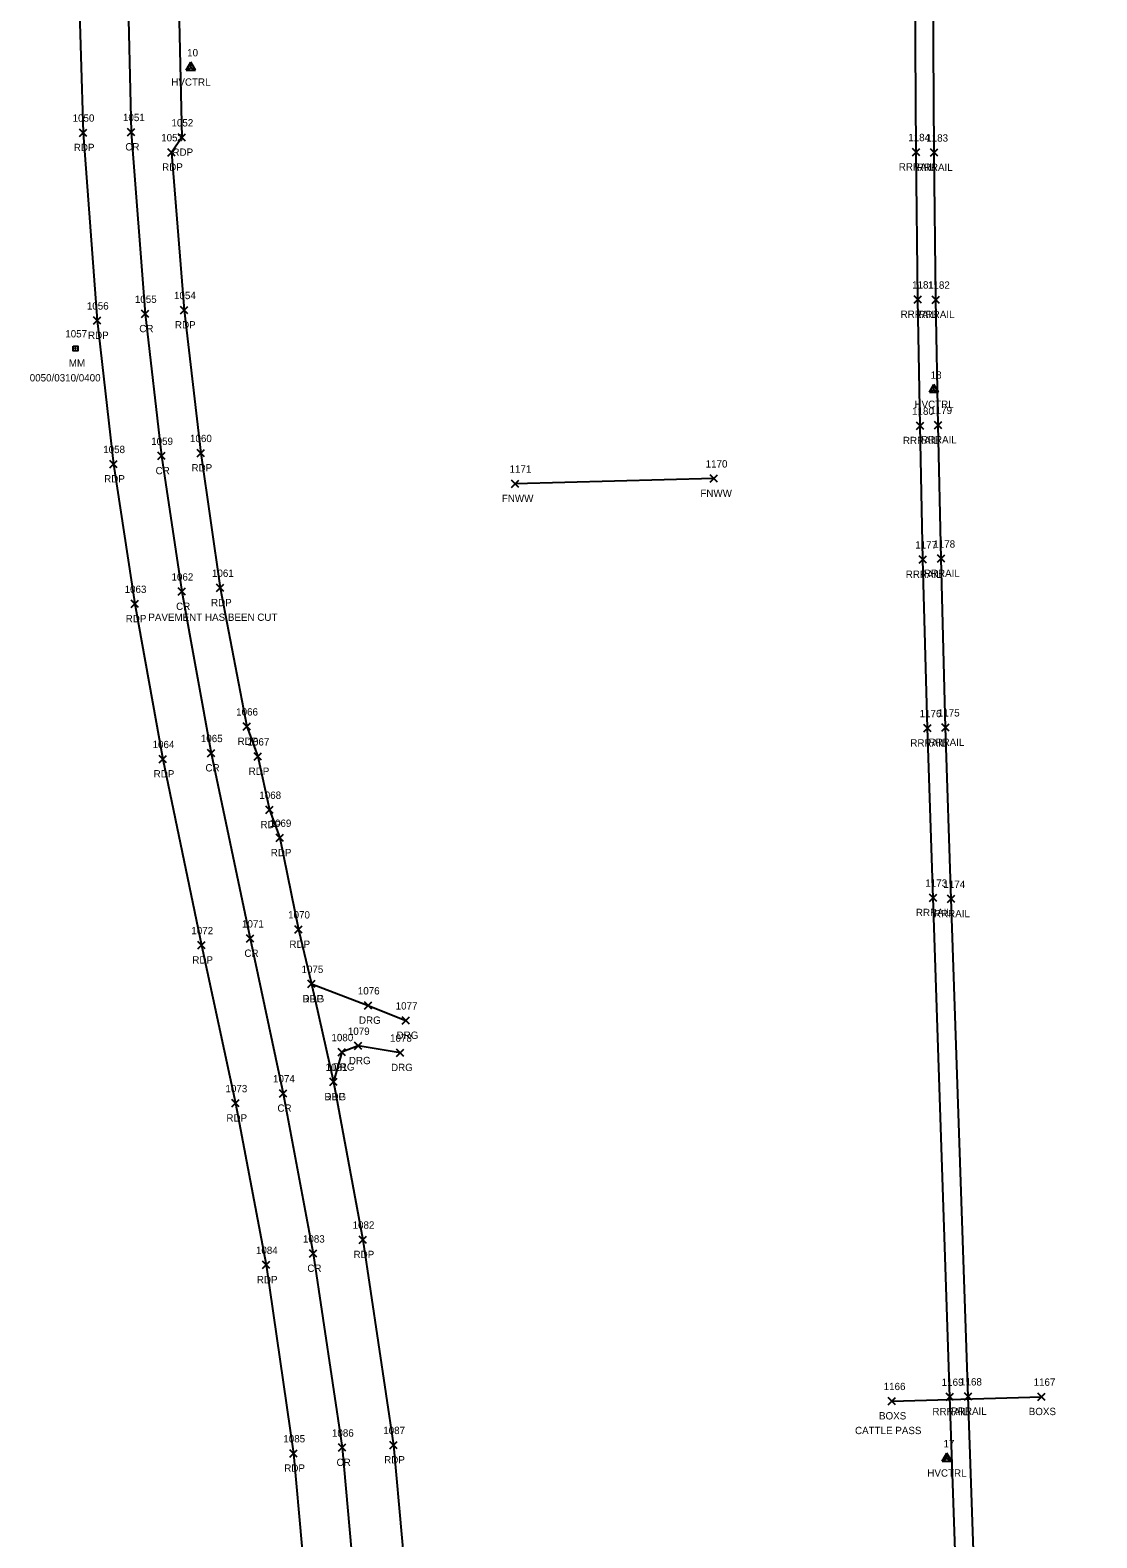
# Model space of a CAD drawing. Extents: x 1754529 to 1755810, y 621660 to 624656.
# Drawn here: x 1755362.7 to 1755653.8, y 622749.4 to 623160.6 of the extents above; entities that cross this region are included whole.
import ezdxf

# ---------------------------------------------------------------- set-up
doc = ezdxf.new("R2010")
doc.units = 0
for name, color, linetype in [('C_A', 7, 'Continuous'), ('C_I', 7, 'Continuous'), ('CPSM', 7, 'Continuous'), ('D_A', 7, 'Continuous'), ('D_C', 7, 'Continuous'), ('D_I', 7, 'Continuous'), ('D_TIC', 7, 'Continuous'), ('DDEFAULT', 7, 'Continuous'), ('L_A', 7, 'Continuous'), ('L_I', 7, 'Continuous'), ('L_TIC', 7, 'Continuous'), ('Level 14', 7, 'Continuous'), ('LFNC', 7, 'Continuous'), ('P_A', 7, 'Continuous'), ('P_C', 7, 'Continuous'), ('P_I', 7, 'Continuous'), ('PET', 7, 'Continuous'), ('PRC', 7, 'Continuous'), ('R_A', 7, 'Continuous'), ('R_I', 7, 'Continuous'), ('R_TIC', 7, 'Continuous'), ('RDG', 7, 'Continuous'), ('RR', 7, 'Continuous'), ('S_A', 7, 'Continuous'), ('S_C', 7, 'Continuous'), ('S_I', 7, 'Continuous'), ('SRM', 7, 'Continuous')]:
    doc.layers.add(name, color=color, linetype=linetype)

msp = doc.modelspace()

# ---------------------------------------------------------------- linework, layer by layer
at = {"layer": 'CPSM'}
for p, q in [((1755405.34, 623149.68), (1755406.59, 623151.85)), ((1755407.84, 623149.68), (1755406.59, 623151.85)), ((1755406.59, 623150.4), (1755406.59, 623151.85)), ((1755405.34, 623149.68), (1755406.59, 623150.4)), ((1755405.34, 623149.68), (1755407.84, 623149.68)), ((1755406.59, 623150.4), (1755406.59, 623150.4)), ((1755406.59, 623150.4), (1755407.84, 623149.68)), ((1755608.13, 623061.8), (1755609.38, 623063.97)), ((1755608.13, 623061.8), (1755609.38, 623062.52)), ((1755608.13, 623061.8), (1755610.63, 623061.8)), ((1755610.63, 623061.8), (1755609.38, 623063.97)), ((1755609.38, 623062.52), (1755609.38, 623063.97)), ((1755609.38, 623062.52), (1755609.38, 623062.52)), ((1755609.38, 623062.52), (1755610.63, 623061.8)), ((1755611.64, 622770.39), (1755612.89, 622772.56)), ((1755611.64, 622770.39), (1755612.89, 622771.12)), ((1755611.64, 622770.39), (1755614.14, 622770.39)), ((1755614.14, 622770.39), (1755612.89, 622772.56)), ((1755612.89, 622771.12), (1755612.89, 622772.56)), ((1755612.89, 622771.12), (1755612.89, 622771.12)), ((1755612.89, 622771.12), (1755614.14, 622770.39))]:
    msp.add_line(p, q, dxfattribs=at)
at = {"layer": 'D_TIC'}
for points in [[(1755596.89, 622785.72), (1755598.89, 622787.72)], [(1755598.89, 622785.72), (1755596.89, 622787.72)], [(1755637.74, 622786.9), (1755639.74, 622788.9)], [(1755639.74, 622786.9), (1755637.74, 622788.9)]]:
    msp.add_lwpolyline(points, dxfattribs=at)
at = {"layer": 'DDEFAULT'}
msp.add_lwpolyline([(1755597.89, 622786.72), (1755638.74, 622787.9)], dxfattribs=at)
at = {"layer": 'L_TIC'}
for points in [[(1755494.12, 623035.88), (1755496.12, 623037.88)], [(1755496.12, 623035.88), (1755494.12, 623037.88)], [(1755548.29, 623037.29), (1755550.29, 623039.29)], [(1755550.29, 623037.29), (1755548.29, 623039.29)]]:
    msp.add_lwpolyline(points, dxfattribs=at)
at = {"layer": 'Level 14'}
for points in [[(1755376.19, 623131.58), (1755378.19, 623133.58)], [(1755378.19, 623131.58), (1755376.19, 623133.58)], [(1755389.29, 623131.74), (1755391.29, 623133.74)], [(1755391.29, 623131.74), (1755389.29, 623133.74)], [(1755403.1, 623130.29), (1755405.1, 623132.29)], [(1755405.1, 623130.29), (1755403.1, 623132.29)], [(1755400.28, 623126.23), (1755402.28, 623128.23)], [(1755402.28, 623126.23), (1755400.28, 623128.23)], [(1755380.06, 623080.36), (1755382.06, 623082.36)], [(1755382.06, 623080.36), (1755380.06, 623082.36)], [(1755393.1, 623082.18), (1755395.1, 623084.18)], [(1755395.1, 623082.18), (1755393.1, 623084.18)], [(1755403.78, 623083.2), (1755405.78, 623085.2)], [(1755405.78, 623083.2), (1755403.78, 623085.2)], [(1755397.56, 623043.45), (1755399.56, 623045.45)], [(1755399.56, 623043.45), (1755397.56, 623045.45)], [(1755408.29, 623044.22), (1755410.29, 623046.22)], [(1755410.29, 623044.22), (1755408.29, 623046.22)], [(1755384.46, 623041.22), (1755386.46, 623043.22)], [(1755386.46, 623041.22), (1755384.46, 623043.22)], [(1755403.15, 623006.45), (1755405.15, 623008.45)], [(1755405.15, 623006.45), (1755403.15, 623008.45)], [(1755413.62, 623007.47), (1755415.62, 623009.47)], [(1755415.62, 623007.47), (1755413.62, 623009.47)], [(1755390.35, 623003.09), (1755392.35, 623005.09)], [(1755392.35, 623003.09), (1755390.35, 623005.09)], [(1755420.85, 622969.66), (1755422.85, 622971.66)], [(1755422.85, 622969.66), (1755420.85, 622971.66)], [(1755397.98, 622960.77), (1755399.98, 622962.77)], [(1755399.98, 622960.77), (1755397.98, 622962.77)], [(1755411.15, 622962.41), (1755413.15, 622964.41)], [(1755413.15, 622962.41), (1755411.15, 622964.41)], [(1755423.89, 622961.49), (1755425.89, 622963.49)], [(1755425.89, 622961.49), (1755423.89, 622963.49)], [(1755427.11, 622946.94), (1755429.11, 622948.94)], [(1755429.11, 622946.94), (1755427.11, 622948.94)], [(1755429.91, 622939.3), (1755431.91, 622941.3)], [(1755431.91, 622939.3), (1755429.91, 622941.3)], [(1755421.77, 622911.86), (1755423.77, 622913.86)], [(1755423.77, 622911.86), (1755421.77, 622913.86)], [(1755435.01, 622914.32), (1755437.01, 622916.32)], [(1755437.01, 622914.32), (1755435.01, 622916.32)], [(1755408.52, 622910.02), (1755410.52, 622912.02)], [(1755410.52, 622910.02), (1755408.52, 622912.02)], [(1755438.57, 622899.46), (1755440.57, 622901.46)], [(1755440.57, 622899.46), (1755438.57, 622901.46)], [(1755444.56, 622872.75), (1755446.56, 622874.75)], [(1755446.56, 622872.75), (1755444.56, 622874.75)], [(1755417.82, 622866.94), (1755419.82, 622868.94)], [(1755419.82, 622866.94), (1755417.82, 622868.94)], [(1755430.8, 622869.62), (1755432.8, 622871.62)], [(1755432.8, 622869.62), (1755430.8, 622871.62)], [(1755452.51, 622829.73), (1755454.51, 622831.73)], [(1755454.51, 622829.73), (1755452.51, 622831.73)], [(1755438.96, 622825.95), (1755440.96, 622827.95)], [(1755440.96, 622825.95), (1755438.96, 622827.95)], [(1755426.14, 622822.84), (1755428.14, 622824.84)], [(1755428.14, 622822.84), (1755426.14, 622824.84)], [(1755433.61, 622771.46), (1755435.61, 622773.46)], [(1755435.61, 622771.46), (1755433.61, 622773.46)], [(1755446.94, 622773.03), (1755448.94, 622775.03)], [(1755448.94, 622773.03), (1755446.94, 622775.03)], [(1755460.87, 622773.73), (1755462.87, 622775.73)], [(1755462.87, 622773.73), (1755460.87, 622775.73)]]:
    msp.add_lwpolyline(points, dxfattribs=at)
at = {"layer": 'LFNC'}
msp.add_lwpolyline([(1755549.29, 623038.29), (1755495.12, 623036.88)], dxfattribs=at)
at = {"layer": 'PET'}
for points in [[(1755375.95, 623174.43), (1755377.19, 623132.58), (1755381.06, 623081.36), (1755385.46, 623042.22), (1755391.35, 623004.09), (1755398.98, 622961.77), (1755409.52, 622911.02), (1755418.82, 622867.94), (1755427.14, 622823.84), (1755434.61, 622772.46), (1755439.16, 622721.92), (1755440.41, 622674.08), (1755439.3, 622634.75), (1755436.09, 622590.86), (1755430.4, 622550.56), (1755422.04, 622511.78), (1755410.15, 622467.07), (1755398.03, 622428.72), (1755382.8, 622387.37), (1755367.12, 622350.92)], [(1755403.14, 623175.05), (1755404.1, 623131.29), (1755401.28, 623127.23), (1755404.78, 623084.2), (1755409.29, 623045.22), (1755414.62, 623008.47), (1755421.85, 622970.66), (1755424.89, 622962.49), (1755428.11, 622947.94), (1755430.91, 622940.3), (1755436.01, 622915.32), (1755439.57, 622900.46), (1755445.56, 622873.75), (1755453.51, 622830.73), (1755461.87, 622774.73), (1755466.46, 622724.18)]]:
    msp.add_lwpolyline(points, dxfattribs=at)
at = {"layer": 'PRC'}
msp.add_lwpolyline([(1755389.28, 623175.01), (1755390.29, 623132.74), (1755394.1, 623083.18), (1755398.56, 623044.45), (1755404.15, 623007.45), (1755412.15, 622963.41), (1755422.77, 622912.86), (1755431.8, 622870.62), (1755439.96, 622826.95), (1755447.94, 622774.03), (1755452.46, 622723.25), (1755453.82, 622673.68), (1755452.65, 622634.4), (1755449.17, 622589.49), (1755443.6, 622548.85), (1755434.83, 622508.14), (1755423.27, 622464.21), (1755410.58, 622424.75), (1755395.16, 622382.85), (1755378.9, 622345.47)], dxfattribs=at)
at = {"layer": 'R_TIC'}
for points in [[(1755603.49, 623126.28), (1755605.49, 623128.28)], [(1755605.49, 623126.28), (1755603.49, 623128.28)], [(1755608.4, 623126.16), (1755610.4, 623128.16)], [(1755610.4, 623126.16), (1755608.4, 623128.16)], [(1755603.97, 623086.09), (1755605.97, 623088.09)], [(1755605.97, 623086.09), (1755603.97, 623088.09)], [(1755608.89, 623086.03), (1755610.89, 623088.03)], [(1755610.89, 623086.03), (1755608.89, 623088.03)], [(1755604.63, 623051.66), (1755606.63, 623053.66)], [(1755606.63, 623051.66), (1755604.63, 623053.66)], [(1755609.51, 623051.88), (1755611.51, 623053.88)], [(1755611.51, 623051.88), (1755609.51, 623053.88)], [(1755605.39, 623015.18), (1755607.39, 623017.18)], [(1755607.39, 623015.18), (1755605.39, 623017.18)], [(1755610.33, 623015.44), (1755612.33, 623017.44)], [(1755612.33, 623015.44), (1755610.33, 623017.44)], [(1755606.65, 622969.2), (1755608.65, 622971.2)], [(1755608.65, 622969.2), (1755606.65, 622971.2)], [(1755611.57, 622969.4), (1755613.57, 622971.4)], [(1755613.57, 622969.4), (1755611.57, 622971.4)], [(1755608.16, 622922.97), (1755610.16, 622924.97)], [(1755610.16, 622922.97), (1755608.16, 622924.97)], [(1755613.09, 622922.65), (1755615.09, 622924.65)], [(1755615.09, 622922.65), (1755613.09, 622924.65)], [(1755438.57, 622899.46), (1755440.57, 622901.46)], [(1755440.57, 622899.46), (1755438.57, 622901.46)], [(1755454, 622893.6), (1755456, 622895.6)], [(1755456, 622893.6), (1755454, 622895.6)], [(1755464.26, 622889.49), (1755466.26, 622891.49)], [(1755466.26, 622889.49), (1755464.26, 622891.49)], [(1755451.23, 622882.59), (1755453.23, 622884.59)], [(1755453.23, 622882.59), (1755451.23, 622884.59)], [(1755446.83, 622880.86), (1755448.83, 622882.86)], [(1755448.83, 622880.86), (1755446.83, 622882.86)], [(1755462.74, 622880.72), (1755464.74, 622882.72)], [(1755464.74, 622880.72), (1755462.74, 622882.72)], [(1755444.56, 622872.75), (1755446.56, 622874.75)], [(1755446.56, 622872.75), (1755444.56, 622874.75)], [(1755612.67, 622786.88), (1755614.67, 622788.88)], [(1755614.67, 622786.88), (1755612.67, 622788.88)], [(1755617.69, 622786.98), (1755619.69, 622788.98)], [(1755619.69, 622786.98), (1755617.69, 622788.98)]]:
    msp.add_lwpolyline(points, dxfattribs=at)
at = {"layer": 'RDG'}
for points in [[(1755439.57, 622900.46), (1755455, 622894.6), (1755465.26, 622890.49)], [(1755463.74, 622881.72), (1755452.23, 622883.59), (1755447.83, 622881.86), (1755445.56, 622873.75)]]:
    msp.add_lwpolyline(points, dxfattribs=at)
at = {"layer": 'RR'}
for points in [[(1755648.95, 621764.81), (1755636.45, 622131.43), (1755613.67, 622787.88), (1755609.16, 622923.97), (1755607.65, 622970.2), (1755606.39, 623016.18), (1755605.63, 623052.66), (1755604.97, 623087.09), (1755604.49, 623127.28), (1755604.22, 623170.71)], [(1755653.84, 621764.86), (1755641.42, 622131.55), (1755638.13, 622228.47), (1755618.69, 622787.98), (1755614.09, 622923.65), (1755612.57, 622970.4), (1755611.33, 623016.44), (1755610.51, 623052.88), (1755609.89, 623087.03), (1755609.4, 623127.16), (1755609.16, 623170.67)]]:
    msp.add_lwpolyline(points, dxfattribs=at)
at = {"layer": 'SRM'}
msp.add_lwpolyline([(1755374.48, 623074.38), (1755375.73, 623074.38), (1755375.73, 623073.13), (1755374.48, 623073.13)], close=True, dxfattribs=at)
msp.add_circle((1755375.11, 623073.76), 0.0833, dxfattribs=at)

# ---------------------------------------------------------------- texts
at = {"layer": 'C_A'}
for p in [(1755401.28, 623145.4), (1755604.07, 623057.52), (1755607.58, 622766.12)]:
    msp.add_text('HVCTRL', height=2, dxfattribs=at).set_placement(p)
at = {"layer": 'C_I'}
for s, p in [('10', (1755405.6, 623153.4)), ('18', (1755608.48, 623065.52)), ('17', (1755611.99, 622774.12))]:
    msp.add_text(s, height=2, dxfattribs=at).set_placement(p)
at = {"layer": 'D_A'}
for p in [(1755594.39, 622781.72), (1755635.25, 622782.9)]:
    msp.add_text('BOXS', height=2, dxfattribs=at).set_placement(p)
at = {"layer": 'D_C'}
msp.add_text('CATTLE PASS', height=2, dxfattribs=at).set_placement((1755587.84, 622777.72))
at = {"layer": 'D_I'}
for s, p in [('1166', (1755595.66, 622789.72)), ('1167', (1755636.57, 622790.9))]:
    msp.add_text(s, height=2, dxfattribs=at).set_placement(p)
at = {"layer": 'L_A'}
for p in [(1755491.47, 623031.88), (1755545.64, 623033.29)]:
    msp.add_text('FNWW', height=2, dxfattribs=at).set_placement(p)
at = {"layer": 'L_I'}
for s, p in [('1171', (1755493.56, 623039.88)), ('1170', (1755547.08, 623041.29))]:
    msp.add_text(s, height=2, dxfattribs=at).set_placement(p)
at = {"layer": 'P_A'}
for s, p in [('RDP', (1755374.67, 623127.58)), ('CR', (1755388.72, 623127.74)), ('RDP', (1755401.58, 623126.29)), ('RDP', (1755398.77, 623122.23)), ('RDP', (1755378.54, 623076.36)), ('CR', (1755392.53, 623078.18)), ('RDP', (1755402.27, 623079.2)), ('CR', (1755396.99, 623039.45)), ('RDP', (1755406.78, 623040.22)), ('RDP', (1755382.95, 623037.22)), ('CR', (1755402.58, 623002.45)), ('RDP', (1755412.11, 623003.47)), ('RDP', (1755388.83, 622999.09)), ('RDP', (1755419.34, 622965.66)), ('RDP', (1755396.46, 622956.77)), ('CR', (1755410.59, 622958.41)), ('RDP', (1755422.37, 622957.49)), ('RDP', (1755425.6, 622942.94)), ('RDP', (1755428.4, 622935.3)), ('CR', (1755421.21, 622907.86)), ('RDP', (1755433.5, 622910.32)), ('RDP', (1755407, 622906.02)), ('RDP', (1755437.06, 622895.46)), ('RDP', (1755443.04, 622868.75)), ('RDP', (1755416.31, 622862.94)), ('CR', (1755430.23, 622865.62)), ('RDP', (1755451, 622825.73)), ('CR', (1755438.39, 622821.95)), ('RDP', (1755424.62, 622818.84)), ('RDP', (1755432.1, 622767.46)), ('CR', (1755446.37, 622769.03)), ('RDP', (1755459.36, 622769.73))]:
    msp.add_text(s, height=2, dxfattribs=at).set_placement(p)
at = {"layer": 'P_C'}
msp.add_text('PAVEMENT HAS BEEN CUT', height=2, dxfattribs=at).set_placement((1755395.01, 622999.47))
at = {"layer": 'P_I'}
for s, p in [('1050', (1755374.33, 623135.58)), ('1051', (1755388.08, 623135.74)), ('1052', (1755401.32, 623134.29)), ('1053', (1755398.51, 623130.23)), ('1056', (1755378.23, 623084.36)), ('1055', (1755391.33, 623086.18)), ('1054', (1755402.01, 623087.2)), ('1059', (1755395.78, 623047.45)), ('1060', (1755406.38, 623048.22)), ('1058', (1755382.69, 623045.22)), ('1062', (1755401.33, 623010.45)), ('1061', (1755412.37, 623011.47)), ('1063', (1755388.53, 623007.09)), ('1066', (1755418.97, 622973.66)), ('1064', (1755396.16, 622964.77)), ('1065', (1755409.33, 622966.41)), ('1067', (1755422.07, 622965.49)), ('1068', (1755425.29, 622950.94)), ('1069', (1755428.08, 622943.3)), ('1071', (1755420.57, 622915.86)), ('1070', (1755433.15, 622918.32)), ('1072', (1755406.74, 622914.02)), ('1075', (1755436.8, 622903.46)), ('1081', (1755443.35, 622876.75)), ('1073', (1755416.05, 622870.94)), ('1074', (1755429.03, 622873.62)), ('1082', (1755450.74, 622833.73)), ('1083', (1755437.19, 622829.95)), ('1084', (1755424.36, 622826.84)), ('1085', (1755431.84, 622775.46)), ('1086', (1755445.11, 622777.03)), ('1087', (1755459.1, 622777.73))]:
    msp.add_text(s, height=2, dxfattribs=at).set_placement(p)
at = {"layer": 'R_A'}
for s, p in [('RRRAIL', (1755599.78, 623122.28)), ('RRRAIL', (1755604.69, 623122.16)), ('RRRAIL', (1755600.27, 623082.09)), ('RRRAIL', (1755605.18, 623082.03)), ('RRRAIL', (1755600.92, 623047.66)), ('RRRAIL', (1755605.8, 623047.88)), ('RRRAIL', (1755601.69, 623011.18)), ('RRRAIL', (1755606.63, 623011.44)), ('RRRAIL', (1755602.94, 622965.2)), ('RRRAIL', (1755607.86, 622965.4)), ('RRRAIL', (1755604.45, 622918.97)), ('RRRAIL', (1755609.38, 622918.65)), ('DRG', (1755437.06, 622895.46)), ('DRG', (1755452.48, 622889.6)), ('DRG', (1755462.75, 622885.49)), ('DRG', (1755449.72, 622878.59)), ('DRG', (1755445.32, 622876.86)), ('DRG', (1755461.23, 622876.72)), ('DRG', (1755443.04, 622868.75)), ('RRRAIL', (1755608.96, 622782.88)), ('RRRAIL', (1755613.98, 622782.98))]:
    msp.add_text(s, height=2, dxfattribs=at).set_placement(p)
at = {"layer": 'R_I'}
for s, p in [('1184', (1755602.36, 623130.28)), ('1183', (1755607.28, 623130.16)), ('1181', (1755603.42, 623090.09)), ('1182', (1755607.76, 623090.03)), ('1180', (1755603.41, 623055.66)), ('1179', (1755608.38, 623055.88)), ('1177', (1755604.27, 623019.18)), ('1178', (1755609.21, 623019.44)), ('1176', (1755605.47, 622973.2)), ('1175', (1755610.44, 622973.4)), ('1173', (1755607.03, 622926.97)), ('1174', (1755611.96, 622926.65)), ('1075', (1755436.8, 622903.46)), ('1076', (1755452.17, 622897.6)), ('1077', (1755462.49, 622893.49)), ('1079', (1755449.45, 622886.59)), ('1080', (1755444.97, 622884.86)), ('1078', (1755460.97, 622884.72)), ('1081', (1755443.35, 622876.75)), ('1169', (1755611.49, 622790.88)), ('1168', (1755616.51, 622790.98))]:
    msp.add_text(s, height=2, dxfattribs=at).set_placement(p)
at = {"layer": 'S_A'}
msp.add_text('MM', height=2, dxfattribs=at).set_placement((1755373.3, 623068.76))
at = {"layer": 'S_C'}
msp.add_text('0050/0310/0400', height=2, dxfattribs=at).set_placement((1755362.64, 623064.76))
at = {"layer": 'S_I'}
msp.add_text('1057', height=2, dxfattribs=at).set_placement((1755372.34, 623076.76))

doc.saveas('drawing.dxf')
